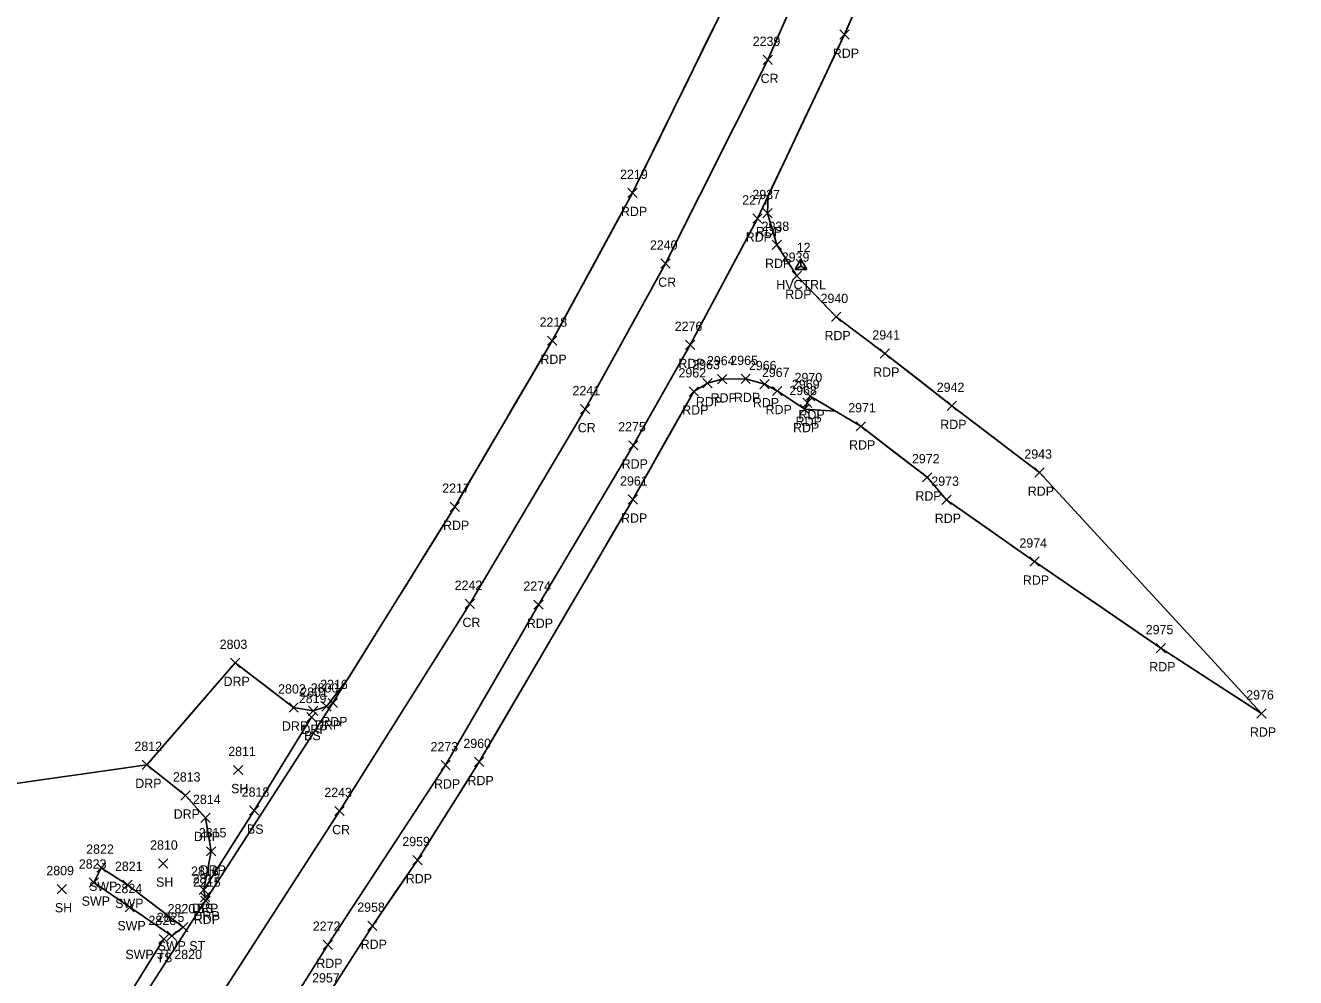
# Model space of a CAD drawing. Extents: x 1638344 to 1639591, y 610835 to 612202.
# Drawn here: x 1639154.7 to 1639428.5, y 611382.3 to 611587.5 of the extents above; entities that cross this region are included whole.
import ezdxf

# ---------------------------------------------------------------- set-up
doc = ezdxf.new("R2010")
doc.units = 0
for name, color, linetype in [('C_A', 7, 'Continuous'), ('C_I', 7, 'Continuous'), ('CPSM', 7, 'Continuous'), ('L_A', 7, 'Continuous'), ('L_I', 7, 'Continuous'), ('L_TIC', 7, 'Continuous'), ('LELB', 7, 'Continuous'), ('LSOGP', 7, 'Continuous'), ('P_A', 7, 'Continuous'), ('P_I', 7, 'Continuous'), ('P_TIC', 7, 'Continuous'), ('PET', 7, 'Continuous'), ('PRC', 7, 'Continuous'), ('R_A', 7, 'Continuous'), ('R_I', 7, 'Continuous'), ('R_TIC', 7, 'Continuous'), ('RDP', 7, 'Continuous'), ('RSW', 7, 'Continuous')]:
    doc.layers.add(name, color=color, linetype=linetype)

msp = doc.modelspace()

# ---------------------------------------------------------------- linework, layer by layer
at = {"layer": 'CPSM'}
for p, q in [((1639320.6, 611534.9), (1639321.85, 611537.06)), ((1639320.6, 611534.9), (1639321.85, 611535.62)), ((1639323.1, 611534.9), (1639321.85, 611537.06)), ((1639321.85, 611535.62), (1639321.85, 611537.06)), ((1639321.85, 611535.62), (1639321.85, 611535.62)), ((1639321.85, 611535.62), (1639323.1, 611534.9)), ((1639320.6, 611534.9), (1639323.1, 611534.9))]:
    msp.add_line(p, q, dxfattribs=at)
at = {"layer": 'L_TIC'}
for points in [[(1639215.31, 611437.44), (1639217.31, 611439.44)], [(1639217.31, 611437.44), (1639215.31, 611439.44)], [(1639199.51, 611426.03), (1639201.51, 611428.03)], [(1639201.51, 611426.03), (1639199.51, 611428.03)], [(1639202.99, 611417.29), (1639204.99, 611419.28)], [(1639204.99, 611417.29), (1639202.99, 611419.28)], [(1639183.34, 611405.87), (1639185.34, 611407.87)], [(1639185.34, 611405.87), (1639183.34, 611407.87)], [(1639161.53, 611400.36), (1639163.53, 611402.36)], [(1639163.53, 611400.36), (1639161.53, 611402.36)], [(1639192.12, 611400.23), (1639194.12, 611402.23)], [(1639194.12, 611400.23), (1639192.12, 611402.23)], [(1639183.51, 611389.62), (1639185.51, 611391.62)], [(1639185.51, 611389.62), (1639183.51, 611391.62)]]:
    msp.add_lwpolyline(points, dxfattribs=at)
at = {"layer": 'LELB'}
for points in [[(1639184.51, 611390.62), (1639168.4, 611364.73), (1639149.11, 611336.39), (1639141.99, 611332.95), (1639134.34, 611331.83), (1639128.54, 611335.12), (1639121.61, 611339.72), (1639110.96, 611351.76), (1639096.79, 611371.21), (1639095.54, 611383.48), (1639101.8, 611394.14), (1639116.54, 611418.41), (1639131.91, 611444.98), (1639113.36, 611469.05), (1639093.12, 611490.67), (1639071.05, 611509.19), (1639055.5, 611526.42)], [(1639193.12, 611401.23), (1639203.99, 611418.29), (1639216.31, 611438.44)]]:
    msp.add_lwpolyline(points, dxfattribs=at)
at = {"layer": 'LSOGP'}
for points in [[(1639219.74, 611378.25), (1639224.6, 611385.86), (1639229.46, 611393.47), (1639234.32, 611400.55), (1639239.18, 611407.62), (1639242.51, 611412.9), (1639245.83, 611418.19), (1639249.16, 611423.47), (1639252.49, 611428.76), (1639256.62, 611435.83), (1639260.76, 611442.9), (1639264.9, 611449.97), (1639269.04, 611457.04), (1639273.18, 611464.11), (1639277.32, 611471.17), (1639281.46, 611478.24), (1639285.6, 611485.31), (1639288.89, 611491.13), (1639292.18, 611496.96), (1639295.48, 611502.78), (1639298.77, 611508.6), (1639301.73, 611510.38), (1639304.9, 611511.21), (1639309.94, 611511.3), (1639314, 611510.18), (1639316.74, 611508.69), (1639322.66, 611504.8), (1639329.29, 611504.34), (1639334.74, 611501.08), (1639341.89, 611495.59), (1639349.04, 611490.09), (1639353.23, 611485.26), (1639357.97, 611481.93), (1639362.72, 611478.6), (1639367.47, 611475.27), (1639372.22, 611471.94), (1639379.03, 611467.27), (1639385.84, 611462.61), (1639392.65, 611457.94), (1639399.45, 611453.28), (1639404.88, 611449.76), (1639410.31, 611446.24), (1639415.74, 611442.73), (1639421.16, 611439.21), (1639373.28, 611491.11), (1639368.56, 611494.7), (1639363.84, 611498.3), (1639359.12, 611501.89), (1639354.4, 611505.49), (1639347.17, 611511.13), (1639339.94, 611516.77), (1639334.69, 611520.71), (1639329.44, 611524.64), (1639325.21, 611529.09), (1639320.99, 611533.53), (1639316.63, 611540.18), (1639314.65, 611547.03), (1639314.81, 611550.81), (1639317.16, 611555.76), (1639319.5, 611560.71), (1639321.85, 611565.67), (1639324.2, 611570.62), (1639326.55, 611575.57), (1639328.89, 611580.52), (1639331.24, 611585.47), (1639333.82, 611591.4)], [(1639303.59, 611588.09), (1639300.58, 611581.98), (1639297.58, 611575.86), (1639294.58, 611569.74), (1639291.58, 611563.62), (1639288.57, 611557.5), (1639285.57, 611551.38), (1639281.23, 611543.42), (1639276.89, 611535.45), (1639272.55, 611527.49), (1639268.2, 611519.53), (1639265.58, 611515.06), (1639262.96, 611510.58), (1639260.33, 611506.11), (1639257.71, 611501.64), (1639255.09, 611497.17), (1639252.46, 611492.7), (1639249.84, 611488.22), (1639247.21, 611483.75), (1639243.93, 611478.47), (1639240.65, 611473.18), (1639237.37, 611467.89), (1639234.09, 611462.61), (1639230.8, 611457.32), (1639227.52, 611452.04), (1639224.24, 611446.75), (1639219.6, 611440.71), (1639216.69, 611439.8), (1639212.49, 611440.5), (1639206.19, 611445.31), (1639199.89, 611450.12), (1639195.13, 611444.63), (1639190.38, 611439.13), (1639185.62, 611433.64), (1639180.86, 611428.14), (1639147.48, 611423.38)]]:
    msp.add_lwpolyline(points, dxfattribs=at)
at = {"layer": 'P_TIC'}
for points in [[(1639330.24, 611584.47), (1639332.24, 611586.47)], [(1639332.24, 611584.47), (1639330.24, 611586.47)], [(1639313.72, 611579.04), (1639315.72, 611581.04)], [(1639315.72, 611579.04), (1639313.72, 611581.04)], [(1639284.57, 611550.38), (1639286.57, 611552.38)], [(1639286.57, 611550.38), (1639284.57, 611552.38)], [(1639311.46, 611544.86), (1639313.46, 611546.86)], [(1639313.46, 611544.86), (1639311.46, 611546.86)], [(1639313.65, 611546.03), (1639315.65, 611548.03)], [(1639315.65, 611546.03), (1639313.65, 611548.03)], [(1639315.63, 611539.18), (1639317.63, 611541.18)], [(1639317.63, 611539.18), (1639315.63, 611541.18)], [(1639291.65, 611535.14), (1639293.65, 611537.14)], [(1639293.65, 611535.14), (1639291.65, 611537.14)], [(1639319.99, 611532.53), (1639321.99, 611534.53)], [(1639321.99, 611532.53), (1639319.99, 611534.53)], [(1639328.44, 611523.64), (1639330.44, 611525.64)], [(1639330.44, 611523.64), (1639328.44, 611525.64)], [(1639267.2, 611518.53), (1639269.2, 611520.53)], [(1639269.2, 611518.53), (1639267.2, 611520.53)], [(1639296.96, 611517.63), (1639298.96, 611519.63)], [(1639298.96, 611517.63), (1639296.96, 611519.63)], [(1639338.94, 611515.77), (1639340.94, 611517.77)], [(1639340.94, 611515.77), (1639338.94, 611517.77)], [(1639300.73, 611509.38), (1639302.73, 611511.38)], [(1639302.73, 611509.38), (1639300.73, 611511.38)], [(1639303.9, 611510.21), (1639305.9, 611512.21)], [(1639305.9, 611510.21), (1639303.9, 611512.21)], [(1639308.94, 611510.3), (1639310.94, 611512.3)], [(1639310.94, 611510.3), (1639308.94, 611512.3)], [(1639313.01, 611509.18), (1639315.01, 611511.18)], [(1639315.01, 611509.18), (1639313.01, 611511.18)], [(1639297.77, 611507.6), (1639299.77, 611509.6)], [(1639299.77, 611507.6), (1639297.77, 611509.6)], [(1639315.74, 611507.69), (1639317.74, 611509.69)], [(1639317.74, 611507.69), (1639315.74, 611509.69)], [(1639322.83, 611506.6), (1639324.83, 611508.59)], [(1639324.83, 611506.6), (1639322.83, 611508.59)], [(1639274.31, 611503.78), (1639276.31, 611505.78)], [(1639276.31, 611503.78), (1639274.31, 611505.78)], [(1639321.66, 611503.8), (1639323.66, 611505.79)], [(1639323.66, 611503.8), (1639321.66, 611505.79)], [(1639322.23, 611505.15), (1639324.22, 611507.15)], [(1639324.22, 611505.15), (1639322.23, 611507.15)], [(1639353.4, 611504.49), (1639355.4, 611506.49)], [(1639355.4, 611504.49), (1639353.4, 611506.49)], [(1639333.74, 611500.08), (1639335.74, 611502.08)], [(1639335.74, 611500.08), (1639333.74, 611502.08)], [(1639284.72, 611495.98), (1639286.72, 611497.98)], [(1639286.72, 611495.98), (1639284.72, 611497.98)], [(1639372.28, 611490.11), (1639374.28, 611492.11)], [(1639374.28, 611490.11), (1639372.28, 611492.11)], [(1639348.04, 611489.09), (1639350.04, 611491.09)], [(1639350.04, 611489.09), (1639348.04, 611491.09)], [(1639284.6, 611484.31), (1639286.6, 611486.31)], [(1639286.6, 611484.31), (1639284.6, 611486.31)], [(1639352.23, 611484.26), (1639354.22, 611486.26)], [(1639354.22, 611484.26), (1639352.23, 611486.26)], [(1639246.21, 611482.75), (1639248.21, 611484.75)], [(1639248.21, 611482.75), (1639246.21, 611484.75)], [(1639371.22, 611470.94), (1639373.22, 611472.94)], [(1639373.22, 611470.94), (1639371.22, 611472.94)], [(1639249.46, 611461.84), (1639251.46, 611463.84)], [(1639251.46, 611461.84), (1639249.46, 611463.84)], [(1639264.27, 611461.65), (1639266.27, 611463.64)], [(1639266.27, 611461.65), (1639264.27, 611463.64)], [(1639398.45, 611452.28), (1639400.45, 611454.28)], [(1639400.45, 611452.28), (1639398.45, 611454.28)], [(1639219.96, 611440.47), (1639221.96, 611442.47)], [(1639221.96, 611440.47), (1639219.96, 611442.47)], [(1639420.16, 611438.21), (1639422.16, 611440.21)], [(1639422.16, 611438.21), (1639420.16, 611440.21)], [(1639244.26, 611427.04), (1639246.26, 611429.04)], [(1639246.26, 611427.04), (1639244.26, 611429.04)], [(1639251.49, 611427.76), (1639253.49, 611429.76)], [(1639253.49, 611427.76), (1639251.49, 611429.76)], [(1639221.36, 611417.19), (1639223.36, 611419.19)], [(1639223.36, 611417.19), (1639221.36, 611419.19)], [(1639238.18, 611406.62), (1639240.18, 611408.62)], [(1639240.18, 611406.62), (1639238.18, 611408.62)], [(1639192.48, 611397.88), (1639194.48, 611399.88)], [(1639194.48, 611397.88), (1639192.48, 611399.88)], [(1639228.46, 611392.47), (1639230.46, 611394.47)], [(1639230.46, 611392.47), (1639228.46, 611394.47)], [(1639218.88, 611388.38), (1639220.88, 611390.38)], [(1639220.88, 611388.38), (1639218.88, 611390.38)]]:
    msp.add_lwpolyline(points, dxfattribs=at)
at = {"layer": 'PET'}
for points in [[(1639189.77, 611341.61), (1639219.88, 611389.38), (1639245.26, 611428.04), (1639265.27, 611462.64), (1639285.72, 611496.98), (1639297.96, 611518.63), (1639312.46, 611545.86), (1639331.24, 611585.47), (1639351.91, 611632.94), (1639369.29, 611681.56), (1639385.15, 611732.94), (1639399.72, 611782.78), (1639415.55, 611836.4), (1639431.27, 611887.12), (1639449.51, 611937.71), (1639468.81, 611983.25), (1639484.71, 612016.47), (1639503.94, 612051.42), (1639527.63, 612090.72), (1639556.4, 612135.37), (1639588.32, 612182.52)], [(1639176.42, 611372.36), (1639193.48, 611398.88), (1639220.96, 611441.47), (1639247.21, 611483.75), (1639268.2, 611519.53), (1639285.57, 611551.38), (1639309.59, 611600.33), (1639328.5, 611645.79), (1639344.08, 611688.67), (1639358.64, 611735.43), (1639372.55, 611782.94), (1639389.97, 611841.92), (1639405.55, 611892.01), (1639422.64, 611939.82), (1639441.75, 611985.91), (1639461.99, 612028.31)], [(1639314.65, 611547.03), (1639316.63, 611540.18), (1639320.99, 611533.53), (1639329.44, 611524.64), (1639339.94, 611516.77), (1639354.4, 611505.49), (1639373.28, 611491.11)], [(1639219.74, 611378.25), (1639229.46, 611393.47), (1639239.18, 611407.62), (1639252.49, 611428.76), (1639285.6, 611485.31), (1639298.77, 611508.6), (1639301.73, 611510.38), (1639304.9, 611511.21), (1639309.94, 611511.3), (1639314, 611510.18), (1639316.74, 611508.69), (1639322.66, 611504.8), (1639323.23, 611506.15), (1639323.83, 611507.59), (1639334.74, 611501.08), (1639349.04, 611490.09), (1639353.23, 611485.26), (1639372.22, 611471.94), (1639399.45, 611453.28), (1639421.16, 611439.21)]]:
    msp.add_lwpolyline(points, dxfattribs=at)
at = {"layer": 'PRC'}
msp.add_lwpolyline([(1639473.49, 612022.53), (1639453.52, 611981.45), (1639432.7, 611930.66), (1639416.88, 611885.47), (1639401.13, 611834.82), (1639385.48, 611780.16), (1639369.66, 611726.72), (1639353.84, 611677.52), (1639335.57, 611627.61), (1639314.72, 611580.04), (1639292.65, 611536.14), (1639275.31, 611504.78), (1639250.46, 611462.84), (1639222.36, 611418.19), (1639195.34, 611376.27)], dxfattribs=at)
at = {"layer": 'R_TIC'}
for points in [[(1639198.89, 611449.12), (1639200.89, 611451.12)], [(1639200.89, 611449.12), (1639198.89, 611451.12)], [(1639211.49, 611439.5), (1639213.49, 611441.5)], [(1639213.49, 611439.5), (1639211.49, 611441.5)], [(1639215.69, 611438.8), (1639217.69, 611440.8)], [(1639217.69, 611438.8), (1639215.69, 611440.8)], [(1639218.6, 611439.71), (1639220.6, 611441.71)], [(1639220.6, 611439.71), (1639218.6, 611441.71)], [(1639179.86, 611427.14), (1639181.86, 611429.14)], [(1639181.86, 611427.14), (1639179.86, 611429.14)], [(1639188.15, 611420.54), (1639190.15, 611422.54)], [(1639190.15, 611420.54), (1639188.15, 611422.54)], [(1639192.49, 611415.71), (1639194.49, 611417.71)], [(1639194.49, 611415.71), (1639192.49, 611417.71)], [(1639193.73, 611408.51), (1639195.73, 611410.51)], [(1639195.73, 611408.51), (1639193.73, 611410.51)], [(1639170.03, 611404.99), (1639172.03, 611406.98)], [(1639172.03, 611404.99), (1639170.03, 611406.98)], [(1639168.44, 611401.78), (1639170.44, 611403.78)], [(1639170.44, 611401.78), (1639168.44, 611403.78)], [(1639175.66, 611401.29), (1639177.66, 611403.29)], [(1639177.66, 611401.29), (1639175.66, 611403.29)], [(1639192.12, 611400.23), (1639194.12, 611402.23)], [(1639194.12, 611400.23), (1639192.12, 611402.23)], [(1639176.14, 611396.5), (1639178.14, 611398.5)], [(1639178.14, 611396.5), (1639176.14, 611398.5)], [(1639192.39, 611398.62), (1639194.39, 611400.62)], [(1639194.39, 611398.62), (1639192.39, 611400.62)], [(1639187.67, 611392.16), (1639189.67, 611394.16)], [(1639189.67, 611392.16), (1639187.67, 611394.16)], [(1639185.24, 611390.29), (1639187.24, 611392.29)], [(1639187.24, 611390.29), (1639185.24, 611392.29)]]:
    msp.add_lwpolyline(points, dxfattribs=at)
at = {"layer": 'RDP'}
msp.add_lwpolyline([(1639219.6, 611440.71), (1639216.69, 611439.8), (1639212.49, 611440.5), (1639199.89, 611450.12), (1639180.86, 611428.14), (1639189.15, 611421.54), (1639193.49, 611416.71), (1639194.73, 611409.51), (1639193.12, 611401.23), (1639193.39, 611399.62)], dxfattribs=at)
at = {"layer": 'RSW'}
for points in [[(1639188.67, 611393.16), (1639176.66, 611402.29), (1639171.03, 611405.98), (1639169.44, 611402.78), (1639177.14, 611397.5), (1639186.24, 611391.29)], [(1639186.24, 611391.29), (1639188.67, 611393.16)]]:
    msp.add_lwpolyline(points, dxfattribs=at)

# ---------------------------------------------------------------- texts
at = {"layer": 'C_A'}
msp.add_text('HVCTRL', height=2, dxfattribs=at).set_placement((1639316.54, 611530.62))
at = {"layer": 'C_I'}
msp.add_text('12', height=2, dxfattribs=at).set_placement((1639320.95, 611538.62))
at = {"layer": 'L_A'}
for s, p in [('BS', (1639214.75, 611433.44)), ('SH', (1639199, 611422.03)), ('BS', (1639202.43, 611413.29)), ('SH', (1639182.83, 611401.87)), ('SH', (1639161.02, 611396.36)), ('BS', (1639191.56, 611396.23)), ('TS', (1639182.92, 611385.62))]:
    msp.add_text(s, height=2, dxfattribs=at).set_placement(p)
at = {"layer": 'L_I'}
for s, p in [('2819', (1639213.61, 611441.44)), ('2811', (1639198.39, 611430.03)), ('2818', (1639201.3, 611421.28)), ('2810', (1639181.56, 611409.87)), ('2809', (1639159.18, 611404.36)), ('2816', (1639190.37, 611404.23)), ('2826', (1639181.19, 611393.62))]:
    msp.add_text(s, height=2, dxfattribs=at).set_placement(p)
at = {"layer": 'P_A'}
for s, p in [('RDP', (1639328.73, 611580.47)), ('CR', (1639313.16, 611575.04)), ('RDP', (1639283.06, 611546.38)), ('RDP', (1639312.14, 611542.03)), ('RDP', (1639309.95, 611540.86)), ('RDP', (1639314.12, 611535.18)), ('CR', (1639291.08, 611531.14)), ('RDP', (1639318.48, 611528.53)), ('RDP', (1639326.93, 611519.64)), ('RDP', (1639265.69, 611514.53)), ('RDP', (1639295.45, 611513.63)), ('RDP', (1639337.43, 611511.77)), ('RDP', (1639302.39, 611506.21)), ('RDP', (1639307.42, 611506.3)), ('RDP', (1639296.26, 611503.6)), ('RDP', (1639299.22, 611505.38)), ('RDP', (1639311.49, 611505.18)), ('RDP', (1639314.23, 611503.69)), ('RDP', (1639320.71, 611501.15)), ('RDP', (1639321.32, 611502.59)), ('RDP', (1639351.89, 611500.49)), ('CR', (1639273.74, 611499.78)), ('RDP', (1639320.15, 611499.8)), ('RDP', (1639332.23, 611496.08)), ('RDP', (1639283.21, 611491.98)), ('RDP', (1639346.53, 611485.09)), ('RDP', (1639370.76, 611486.11)), ('RDP', (1639244.7, 611478.75)), ('RDP', (1639283.08, 611480.31)), ('RDP', (1639350.71, 611480.26)), ('RDP', (1639369.71, 611466.94)), ('CR', (1639248.89, 611457.84)), ('RDP', (1639262.76, 611457.65)), ('RDP', (1639396.94, 611448.28)), ('RDP', (1639218.45, 611436.47)), ('RDP', (1639418.65, 611434.21)), ('RDP', (1639249.97, 611423.76)), ('RDP', (1639242.75, 611423.04)), ('CR', (1639220.79, 611413.19)), ('RDP', (1639236.67, 611402.62)), ('RDP', (1639190.97, 611393.88)), ('RDP', (1639226.95, 611388.47)), ('RDP', (1639217.37, 611384.38))]:
    msp.add_text(s, height=2, dxfattribs=at).set_placement(p)
at = {"layer": 'P_I'}
for s, p in [('2239', (1639311.46, 611583.04)), ('2219', (1639282.87, 611554.38)), ('2937', (1639311.39, 611550.03)), ('2277', (1639309.2, 611548.86)), ('2938', (1639313.37, 611543.18)), ('2240', (1639289.3, 611539.14)), ('2939', (1639317.72, 611536.53)), ('2940', (1639326.09, 611527.64)), ('2218', (1639265.51, 611522.53)), ('2276', (1639294.65, 611521.63)), ('2941', (1639337.25, 611519.77)), ('2964', (1639301.6, 611514.21)), ('2965', (1639306.63, 611514.3)), ('2962', (1639295.46, 611511.6)), ('2963', (1639298.42, 611513.38)), ('2966', (1639310.64, 611513.18)), ('2967', (1639313.44, 611511.69)), ('2969', (1639319.91, 611509.15)), ('2970', (1639320.48, 611510.59)), ('2241', (1639272.61, 611507.78)), ('2968', (1639319.35, 611507.8)), ('2942', (1639351.14, 611508.49)), ('2971', (1639332.05, 611504.08)), ('2275', (1639282.46, 611499.98)), ('2972', (1639345.78, 611493.09)), ('2943', (1639370.02, 611494.11)), ('2217', (1639244.52, 611486.75)), ('2961', (1639282.86, 611488.31)), ('2973', (1639349.97, 611488.26)), ('2974', (1639368.96, 611474.94)), ('2242', (1639247.2, 611465.84)), ('2274', (1639262.02, 611465.65)), ('2975', (1639396.19, 611456.28)), ('2216', (1639218.21, 611444.47)), ('2976', (1639417.85, 611442.21)), ('2273', (1639242, 611431.04)), ('2960', (1639249.09, 611431.76)), ('2243', (1639219.1, 611421.19)), ('2959', (1639235.92, 611410.62)), ('2215', (1639190.79, 611401.88)), ('2958', (1639226.2, 611396.47)), ('2272', (1639216.62, 611392.38)), ('2957', (1639216.48, 611381.25))]:
    msp.add_text(s, height=2, dxfattribs=at).set_placement(p)
at = {"layer": 'R_A'}
for s, p in [('DRP', (1639197.38, 611445.12)), ('DRP', (1639209.97, 611435.5)), ('DRP', (1639214.18, 611434.8)), ('DRP', (1639217.09, 611435.71)), ('DRP', (1639178.35, 611423.14)), ('DRP', (1639186.64, 611416.54)), ('DRP', (1639190.98, 611411.71)), ('DRP', (1639192.22, 611404.51)), ('SWP', (1639168.39, 611400.98)), ('SWP', (1639166.8, 611397.78)), ('SWP', (1639174.02, 611397.29)), ('DRP', (1639190.6, 611396.23)), ('DRP', (1639190.88, 611394.62)), ('SWP', (1639174.5, 611392.5)), ('SWP ST', (1639183.16, 611388.16)), ('SWP JT 2820', (1639176.22, 611386.29))]:
    msp.add_text(s, height=2, dxfattribs=at).set_placement(p)
at = {"layer": 'R_I'}
for s, p in [('2803', (1639196.55, 611453.12)), ('2802', (1639209.15, 611443.5)), ('2800', (1639216.18, 611443.71)), ('2801', (1639213.92, 611442.8)), ('2812', (1639178.17, 611431.14)), ('2813', (1639186.46, 611424.54)), ('2814', (1639190.8, 611419.71)), ('2815', (1639192.04, 611412.51)), ('2822', (1639167.77, 611408.98)), ('2823', (1639166.18, 611405.78)), ('2821', (1639173.97, 611405.29)), ('2816', (1639190.37, 611404.23)), ('2817', (1639190.7, 611402.62)), ('2824', (1639173.88, 611400.5)), ('2825', (1639182.98, 611394.29)), ('2820', (1639185.32, 611396.16))]:
    msp.add_text(s, height=2, dxfattribs=at).set_placement(p)

doc.saveas('drawing.dxf')
